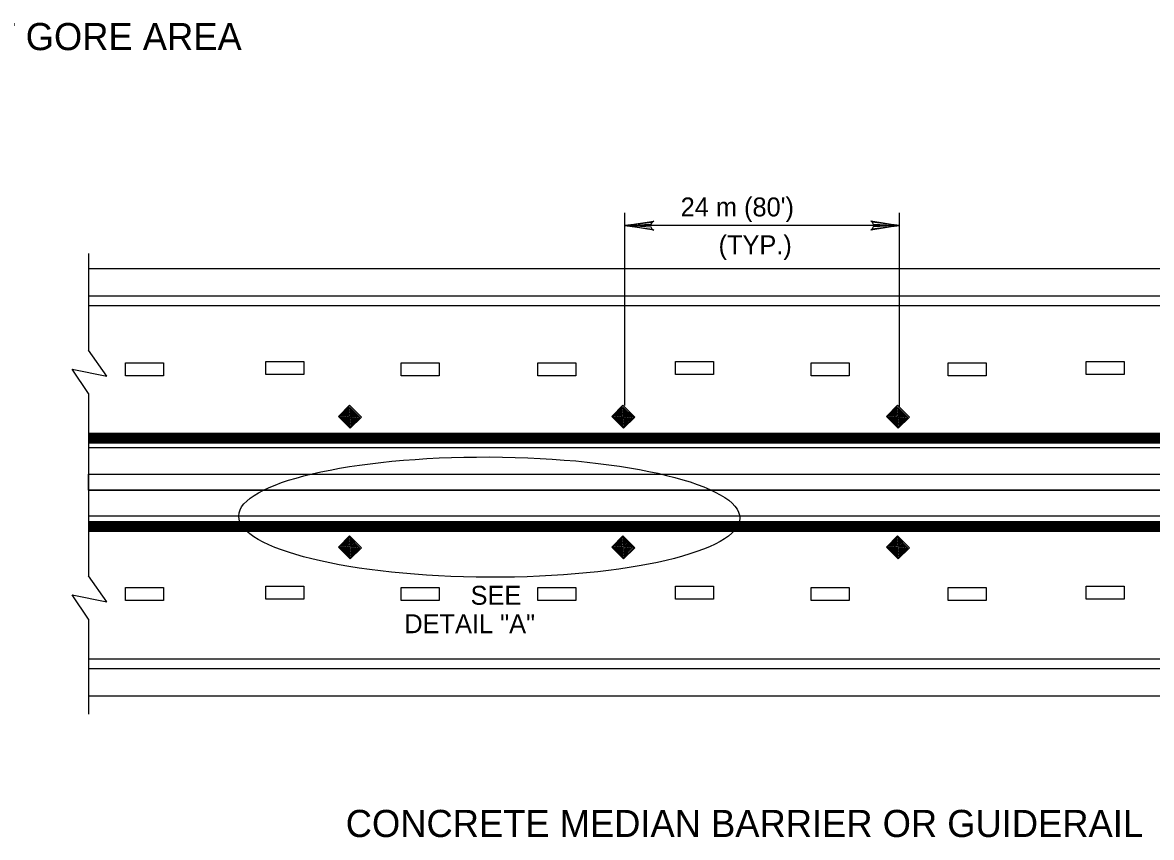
# Model space of a CAD drawing. Extents: x 639362 to 641108, y 298458 to 299646.
# Drawn here: x 639652.3 to 639830.9, y 299351.7 to 299480.8 of the extents above; entities that cross this region are included whole.
import ezdxf

# ---------------------------------------------------------------- set-up
doc = ezdxf.new("R2010")
doc.units = 0
doc.layers.add('2', color=7, linetype='Continuous')

msp = doc.modelspace()

# ---------------------------------------------------------------- linework, layer by layer
at = {"layer": '2'}
for p, q in [((639747.61, 299420.13), (639747.61, 299450.63)), ((639791.05, 299419.91), (639791.05, 299450.63)), ((639791.05, 299448.63), (639747.61, 299448.63)), ((639662.67, 299444.2), (639662.67, 299428.91)), ((639662.67, 299441.83), (639897.17, 299441.83)), ((639662.67, 299437.48), (639897.17, 299437.48)), ((639662.67, 299435.98), (639897.17, 299435.98)), ((639665.62, 299424.78), (639662.67, 299428.91)), ((639690.75, 299425.02), (639690.75, 299427.08)), ((639690.75, 299427.08), (639696.76, 299427.08)), ((639696.76, 299427.08), (639696.76, 299425.02)), ((639755.61, 299425.02), (639755.61, 299427.08)), ((639755.61, 299427.08), (639761.62, 299427.08)), ((639761.62, 299427.08), (639761.62, 299425.02)), ((639820.59, 299425.02), (639820.59, 299427.08)), ((639820.59, 299427.08), (639826.61, 299427.08)), ((639826.61, 299427.08), (639826.61, 299425.02)), ((639662.67, 299422.04), (639660.09, 299425.91)), ((639660.09, 299425.91), (639665.62, 299424.78)), ((639668.56, 299424.83), (639668.56, 299426.9)), ((639668.56, 299426.9), (639674.57, 299426.9)), ((639674.57, 299426.9), (639674.57, 299424.83)), ((639712.2, 299424.83), (639712.2, 299426.9)), ((639712.2, 299426.9), (639718.21, 299426.9)), ((639718.21, 299426.9), (639718.21, 299424.83)), ((639733.83, 299424.83), (639733.83, 299426.9)), ((639733.83, 299426.9), (639739.84, 299426.9)), ((639739.84, 299426.9), (639739.84, 299424.83)), ((639777.06, 299424.83), (639777.06, 299426.9)), ((639777.06, 299426.9), (639783.08, 299426.9)), ((639783.08, 299426.9), (639783.08, 299424.83)), ((639798.78, 299424.83), (639798.78, 299426.9)), ((639798.78, 299426.9), (639804.8, 299426.9)), ((639804.8, 299426.9), (639804.8, 299424.83)), ((639674.57, 299424.83), (639668.56, 299424.83)), ((639696.76, 299425.02), (639690.75, 299425.02)), ((639718.21, 299424.83), (639712.2, 299424.83)), ((639739.84, 299424.83), (639733.83, 299424.83)), ((639761.62, 299425.02), (639755.61, 299425.02)), ((639783.08, 299424.83), (639777.06, 299424.83)), ((639804.8, 299424.83), (639798.78, 299424.83)), ((639826.61, 299425.02), (639820.59, 299425.02)), ((639662.67, 299422.04), (639662.67, 299404.25)), ((639702.24, 299418.4), (639704.01, 299420.17)), ((639702.47, 299418.44), (639703.97, 299419.94)), ((639703.97, 299419.94), (639705.66, 299418.25)), ((639704.01, 299420.17), (639705.88, 299418.29)), ((639745.5, 299418.4), (639747.27, 299420.17)), ((639745.73, 299418.44), (639747.23, 299419.94)), ((639747.23, 299419.94), (639748.93, 299418.25)), ((639747.27, 299420.17), (639749.15, 299418.29)), ((639788.98, 299418.4), (639790.74, 299420.17)), ((639789.2, 299418.44), (639790.7, 299419.94)), ((639790.7, 299419.94), (639792.4, 299418.25)), ((639790.74, 299420.17), (639792.62, 299418.29)), ((639704.12, 299416.53), (639702.24, 299418.4)), ((639704.16, 299416.75), (639702.47, 299418.44)), ((639702.72, 299418.44), (639703.97, 299419.7)), ((639704.16, 299417), (639702.72, 299418.44)), ((639702.97, 299418.44), (639703.97, 299419.44)), ((639704.16, 299417.25), (639702.97, 299418.44)), ((639703.22, 299418.44), (639703.97, 299419.19)), ((639704.16, 299417.5), (639703.22, 299418.44)), ((639703.47, 299418.44), (639703.97, 299418.94)), ((639704.16, 299417.75), (639703.47, 299418.44)), ((639703.72, 299418.44), (639703.97, 299418.69)), ((639704.16, 299418), (639703.72, 299418.44)), ((639703.97, 299419.7), (639705.42, 299418.25)), ((639703.97, 299419.44), (639705.16, 299418.25)), ((639703.97, 299419.19), (639704.91, 299418.25)), ((639703.97, 299418.94), (639704.66, 299418.25)), ((639703.97, 299418.69), (639704.41, 299418.25)), ((639703.97, 299418.44), (639704.16, 299418.25)), ((639705.88, 299418.29), (639704.12, 299416.53)), ((639705.66, 299418.25), (639704.16, 299416.75)), ((639705.42, 299418.25), (639704.16, 299417)), ((639705.16, 299418.25), (639704.16, 299417.25)), ((639704.91, 299418.25), (639704.16, 299417.5)), ((639704.66, 299418.25), (639704.16, 299417.75)), ((639704.41, 299418.25), (639704.16, 299418)), ((639747.38, 299416.53), (639745.5, 299418.4)), ((639747.42, 299416.75), (639745.73, 299418.44)), ((639745.98, 299418.44), (639747.23, 299419.7)), ((639747.42, 299417), (639745.98, 299418.44)), ((639746.23, 299418.44), (639747.23, 299419.44)), ((639747.42, 299417.25), (639746.23, 299418.44)), ((639746.48, 299418.44), (639747.23, 299419.19)), ((639747.42, 299417.5), (639746.48, 299418.44)), ((639746.73, 299418.44), (639747.23, 299418.94)), ((639747.42, 299417.75), (639746.73, 299418.44)), ((639746.98, 299418.44), (639747.23, 299418.69)), ((639747.42, 299418), (639746.98, 299418.44)), ((639747.23, 299419.7), (639748.68, 299418.25)), ((639747.23, 299419.44), (639748.43, 299418.25)), ((639747.23, 299419.19), (639748.17, 299418.25)), ((639747.23, 299418.94), (639747.92, 299418.25)), ((639747.23, 299418.69), (639747.67, 299418.25)), ((639747.23, 299418.44), (639747.42, 299418.25)), ((639749.15, 299418.29), (639747.38, 299416.53)), ((639748.93, 299418.25), (639747.42, 299416.75)), ((639748.68, 299418.25), (639747.42, 299417)), ((639748.43, 299418.25), (639747.42, 299417.25)), ((639748.17, 299418.25), (639747.42, 299417.5)), ((639747.92, 299418.25), (639747.42, 299417.75)), ((639747.67, 299418.25), (639747.42, 299418)), ((639790.85, 299416.53), (639788.98, 299418.4)), ((639790.89, 299416.75), (639789.2, 299418.44)), ((639789.45, 299418.44), (639790.71, 299419.7)), ((639790.89, 299417), (639789.45, 299418.44)), ((639789.7, 299418.44), (639790.71, 299419.44)), ((639790.89, 299417.25), (639789.7, 299418.44)), ((639789.95, 299418.44), (639790.71, 299419.19)), ((639790.89, 299417.5), (639789.95, 299418.44)), ((639790.2, 299418.44), (639790.71, 299418.94)), ((639790.89, 299417.75), (639790.2, 299418.44)), ((639790.45, 299418.44), (639790.7, 299418.69)), ((639790.89, 299418), (639790.45, 299418.44)), ((639790.7, 299418.69), (639791.14, 299418.25)), ((639790.7, 299418.44), (639790.89, 299418.25)), ((639790.71, 299419.7), (639792.15, 299418.25)), ((639790.71, 299419.44), (639791.9, 299418.25)), ((639790.71, 299419.19), (639791.65, 299418.25)), ((639790.71, 299418.94), (639791.39, 299418.25)), ((639792.62, 299418.29), (639790.85, 299416.53)), ((639792.4, 299418.25), (639790.89, 299416.75)), ((639792.15, 299418.25), (639790.89, 299417)), ((639791.9, 299418.25), (639790.89, 299417.25)), ((639791.65, 299418.25), (639790.89, 299417.5)), ((639791.39, 299418.25), (639790.89, 299417.75)), ((639791.14, 299418.25), (639790.89, 299418)), ((639662.67, 299415.75), (639897.17, 299415.75)), ((639662.67, 299415.6), (639897.17, 299415.6)), ((639662.67, 299415.45), (639897.17, 299415.45)), ((639662.67, 299415.3), (639897.17, 299415.3)), ((639662.67, 299415.15), (639897.17, 299415.15)), ((639662.67, 299415), (639897.17, 299415)), ((639662.67, 299414.85), (639897.17, 299414.85)), ((639662.67, 299414.7), (639897.17, 299414.7)), ((639662.67, 299414.55), (639897.17, 299414.55)), ((639662.67, 299414.4), (639897.17, 299414.4)), ((639662.67, 299414.25), (639897.17, 299414.25)), ((639662.67, 299413.5), (639897.17, 299413.5)), ((639662.67, 299409.25), (639897.17, 299409.25)), ((639662.67, 299406.75), (639662.67, 299393.18)), ((639662.67, 299406.75), (639897.17, 299406.75)), ((639662.67, 299402.65), (639897.17, 299402.65)), ((639662.67, 299401.75), (639897.17, 299401.75)), ((639662.67, 299401.75), (639897.17, 299401.75)), ((639662.67, 299401.75), (639897.17, 299401.75)), ((639662.67, 299401.6), (639897.17, 299401.6)), ((639662.67, 299401.45), (639897.17, 299401.45)), ((639662.67, 299401.3), (639897.17, 299401.3)), ((639662.67, 299401.15), (639897.17, 299401.15)), ((639662.67, 299401), (639897.17, 299401)), ((639662.67, 299400.85), (639897.17, 299400.85)), ((639662.67, 299400.7), (639897.17, 299400.7)), ((639662.67, 299400.55), (639897.17, 299400.55)), ((639662.67, 299400.4), (639897.17, 299400.4)), ((639662.67, 299400.25), (639897.17, 299400.25)), ((639702.24, 299397.72), (639704.01, 299399.49)), ((639702.47, 299397.76), (639703.97, 299399.27)), ((639702.72, 299397.76), (639703.97, 299399.02)), ((639702.97, 299397.76), (639703.97, 299398.77)), ((639703.22, 299397.76), (639703.97, 299398.52)), ((639703.97, 299399.27), (639705.66, 299397.57)), ((639703.97, 299399.02), (639705.42, 299397.58)), ((639703.97, 299398.77), (639705.16, 299397.58)), ((639703.97, 299398.52), (639704.91, 299397.58)), ((639704.01, 299399.49), (639705.88, 299397.62)), ((639745.5, 299397.72), (639747.27, 299399.49)), ((639745.73, 299397.76), (639747.23, 299399.27)), ((639745.98, 299397.76), (639747.23, 299399.02)), ((639746.23, 299397.76), (639747.23, 299398.77)), ((639746.48, 299397.76), (639747.23, 299398.52)), ((639747.23, 299399.27), (639748.93, 299397.57)), ((639747.23, 299399.02), (639748.68, 299397.58)), ((639747.23, 299398.77), (639748.43, 299397.58)), ((639747.23, 299398.52), (639748.17, 299397.58)), ((639747.27, 299399.49), (639749.15, 299397.62)), ((639788.98, 299397.72), (639790.74, 299399.49)), ((639789.2, 299397.76), (639790.7, 299399.27)), ((639789.45, 299397.76), (639790.71, 299399.02)), ((639789.7, 299397.76), (639790.71, 299398.77)), ((639789.95, 299397.76), (639790.71, 299398.52)), ((639790.7, 299399.27), (639792.4, 299397.57)), ((639790.71, 299399.02), (639792.15, 299397.58)), ((639790.71, 299398.77), (639791.9, 299397.58)), ((639790.71, 299398.52), (639791.65, 299397.58)), ((639790.74, 299399.49), (639792.62, 299397.62)), ((639704.12, 299395.85), (639702.24, 299397.72)), ((639704.16, 299396.07), (639702.47, 299397.76)), ((639704.16, 299396.32), (639702.72, 299397.76)), ((639704.16, 299396.57), (639702.97, 299397.76)), ((639704.16, 299396.82), (639703.22, 299397.76)), ((639703.47, 299397.76), (639703.97, 299398.26)), ((639704.16, 299397.07), (639703.47, 299397.76)), ((639703.72, 299397.76), (639703.97, 299398.02)), ((639704.16, 299397.32), (639703.72, 299397.76)), ((639703.97, 299398.26), (639704.66, 299397.58)), ((639703.97, 299398.02), (639704.41, 299397.58)), ((639703.97, 299397.76), (639704.16, 299397.57)), ((639705.88, 299397.62), (639704.12, 299395.85)), ((639705.42, 299397.58), (639704.16, 299396.32)), ((639705.16, 299397.58), (639704.16, 299396.57)), ((639704.91, 299397.58), (639704.16, 299396.82)), ((639704.66, 299397.58), (639704.16, 299397.07)), ((639704.41, 299397.58), (639704.16, 299397.32)), ((639705.66, 299397.57), (639704.16, 299396.07)), ((639747.38, 299395.85), (639745.5, 299397.72)), ((639747.42, 299396.07), (639745.73, 299397.76)), ((639747.42, 299396.32), (639745.98, 299397.76)), ((639747.42, 299396.57), (639746.23, 299397.76)), ((639747.42, 299396.82), (639746.48, 299397.76)), ((639746.73, 299397.76), (639747.23, 299398.26)), ((639747.42, 299397.07), (639746.73, 299397.76)), ((639746.98, 299397.76), (639747.23, 299398.02)), ((639747.42, 299397.32), (639746.98, 299397.76)), ((639747.23, 299398.26), (639747.92, 299397.58)), ((639747.23, 299398.02), (639747.67, 299397.58)), ((639747.23, 299397.76), (639747.42, 299397.57)), ((639749.15, 299397.62), (639747.38, 299395.85)), ((639748.68, 299397.58), (639747.42, 299396.32)), ((639748.43, 299397.58), (639747.42, 299396.57)), ((639748.17, 299397.58), (639747.42, 299396.82)), ((639747.92, 299397.58), (639747.42, 299397.07)), ((639747.67, 299397.58), (639747.42, 299397.32)), ((639748.93, 299397.57), (639747.42, 299396.07)), ((639790.85, 299395.85), (639788.98, 299397.72)), ((639790.89, 299396.07), (639789.2, 299397.76)), ((639790.89, 299396.32), (639789.45, 299397.76)), ((639790.89, 299396.57), (639789.7, 299397.76)), ((639790.89, 299396.82), (639789.95, 299397.76)), ((639790.2, 299397.76), (639790.71, 299398.26)), ((639790.89, 299397.07), (639790.2, 299397.76)), ((639790.45, 299397.76), (639790.7, 299398.02)), ((639790.89, 299397.32), (639790.45, 299397.76)), ((639790.7, 299398.02), (639791.14, 299397.58)), ((639790.7, 299397.76), (639790.89, 299397.57)), ((639790.71, 299398.26), (639791.39, 299397.58)), ((639792.62, 299397.62), (639790.85, 299395.85)), ((639792.15, 299397.58), (639790.89, 299396.32)), ((639791.9, 299397.58), (639790.89, 299396.57)), ((639791.65, 299397.58), (639790.89, 299396.82)), ((639791.39, 299397.58), (639790.89, 299397.07)), ((639791.14, 299397.58), (639790.89, 299397.32)), ((639792.4, 299397.57), (639790.89, 299396.07)), ((639665.62, 299389.05), (639662.67, 299393.18)), ((639668.56, 299389.26), (639668.56, 299391.32)), ((639668.56, 299391.32), (639674.57, 299391.32)), ((639674.57, 299391.32), (639674.57, 299389.26)), ((639690.75, 299389.45), (639690.75, 299391.51)), ((639690.75, 299391.51), (639696.76, 299391.51)), ((639696.76, 299391.51), (639696.76, 299389.45)), ((639712.2, 299389.26), (639712.2, 299391.32)), ((639712.2, 299391.32), (639718.21, 299391.32)), ((639718.21, 299391.32), (639718.21, 299389.26)), ((639733.83, 299389.26), (639733.83, 299391.32)), ((639733.83, 299391.32), (639739.84, 299391.32)), ((639739.84, 299391.32), (639739.84, 299389.26)), ((639755.61, 299389.45), (639755.61, 299391.51)), ((639755.61, 299391.51), (639761.62, 299391.51)), ((639761.62, 299391.51), (639761.62, 299389.45)), ((639777.06, 299389.26), (639777.06, 299391.32)), ((639777.06, 299391.32), (639783.08, 299391.32)), ((639783.08, 299391.32), (639783.08, 299389.26)), ((639798.78, 299389.26), (639798.78, 299391.32)), ((639798.78, 299391.32), (639804.8, 299391.32)), ((639804.8, 299391.32), (639804.8, 299389.26)), ((639820.59, 299389.45), (639820.59, 299391.51)), ((639820.59, 299391.51), (639826.61, 299391.51)), ((639826.61, 299391.51), (639826.61, 299389.45)), ((639662.67, 299386.31), (639660.09, 299390.18)), ((639660.09, 299390.18), (639665.62, 299389.05)), ((639674.57, 299389.26), (639668.56, 299389.26)), ((639696.76, 299389.45), (639690.75, 299389.45)), ((639718.21, 299389.26), (639712.2, 299389.26)), ((639739.84, 299389.26), (639733.83, 299389.26)), ((639761.62, 299389.45), (639755.61, 299389.45)), ((639783.08, 299389.26), (639777.06, 299389.26)), ((639804.8, 299389.26), (639798.78, 299389.26)), ((639826.61, 299389.45), (639820.59, 299389.45)), ((639662.67, 299386.31), (639662.67, 299371.24)), ((639662.67, 299380.01), (639897.17, 299380.01)), ((639662.67, 299378.51), (639897.17, 299378.51)), ((639662.67, 299374.16), (639897.17, 299374.16))]:
    msp.add_line(p, q, dxfattribs=at)
for points in [[(639751.93, 299448.08), (639751.77, 299448.4), (639747.61, 299448.63), (639751.93, 299448.08), (639752.15, 299447.89), (639747.61, 299448.63), (639751.77, 299448.83), (639751.92, 299449.14), (639747.61, 299448.63), (639752.15, 299449.35), (639751.92, 299449.14)], [(639786.73, 299449.17), (639786.89, 299448.85), (639791.05, 299448.63), (639786.73, 299449.17), (639786.51, 299449.36), (639791.05, 299448.63), (639786.9, 299448.42), (639786.75, 299448.11), (639791.05, 299448.63), (639786.51, 299447.9), (639786.75, 299448.11)]]:
    msp.add_lwpolyline(points, dxfattribs=at)
msp.add_lwpolyline([(639662.67, 299409.25), (639897.17, 299409.25), (639897.17, 299406.75), (639662.67, 299406.75)], close=True, dxfattribs=at)
msp.add_ellipse((639726.13, 299402.46), major_axis=(39.66, -0.17), ratio=0.240157, dxfattribs=at)

# ---------------------------------------------------------------- texts
for s, height, p in [('EXIT GORE AREA', 4.3, (639638.38, 299476.41)), ("24 m (80')", 3, (639756.42, 299450.08)), ('(TYP.)', 3, (639762.42, 299444.08)), ('SEE', 3, (639723.17, 299388.58)), ('DETAIL "A"', 3, (639712.69, 299384.08)), ('CONCRETE MEDIAN BARRIER OR GUIDERAIL', 4.3, (639703.41, 299351.8))]:
    msp.add_text(s, height=height, dxfattribs=at).set_placement(p)

doc.saveas('drawing.dxf')
